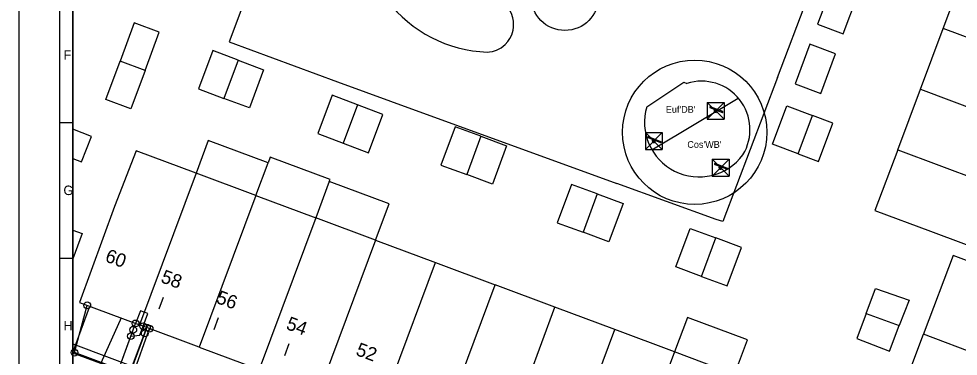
# Model space of a CAD drawing. Extents: x 192672 to 192910, y 446344 to 446512.
# Drawn here: x 192671.7 to 192741.1, y 446430.4 to 446455.3 of the extents above; entities that cross this region are included whole.
import ezdxf

# ---------------------------------------------------------------- set-up
doc = ezdxf.new("R2010")
doc.units = 0
for name, color, linetype in [('1010 viewport', 7, 'Continuous'), ('B-GV-GR-BOOM-S', 7, 'Continuous'), ('B-GV-KG-GRENS_WERKGRENS-G', 7, 'Continuous'), ('B-OI-KL-()_MANTELBUIS_WATER-G', 7, 'Continuous'), ('B-OI-KL-BUISLEIDING_OLIEGASCHEMICALIEN_GASLAGEDRUK-G', 7, 'Continuous'), ('B-OI-KL-DATA-G', 7, 'Continuous'), ('B-OI-KL-DATA_GTWP-S', 7, 'Continuous'), ('B-OI-KL-DATA_KABELBED-G', 7, 'Continuous'), ('B-OI-KL-DATA_MOF-S', 7, 'Continuous'), ('B-OI-KL-ET_LS-G', 7, 'Continuous'), ('B-OI-KL-ET_LS_DELIVERYPOINT-S', 7, 'Continuous'), ('B-OI-KL-ET_LS_MOF-S', 7, 'Continuous'), ('B-OI-KL-GAS_LD_DELIVERYPOINT-S', 7, 'Continuous'), ('B-OI-KL-GAS_LD_OVERGANGSSTUK-S', 7, 'Continuous'), ('B-OI-KL-WATER-G', 7, 'Continuous'), ('Default', 7, 'Continuous'), ('grens maaiveld', 7, 'Continuous'), ('huisnummerreeks BGT', 7, 'Continuous'), ('kant open verharding', 7, 'Continuous'), ('Luifel', 7, 'Continuous'), ('N-GV-GR-BEPLANTING-G', 7, 'Continuous'), ('pand op maaiveld vlak', 7, 'Continuous'), ('speelvoorziening', 7, 'Continuous'), ('TEKST', 7, 'Continuous'), ('V-GV-IE-MEUBILAIR_WEGMEUBILAIR_SPEELTOESTEL-G', 7, 'Continuous'), ('X-XX-AL-TEKENBLAD-S', 7, 'Continuous')]:
    doc.layers.add(name, color=color, linetype=linetype)

# ---------------------------------------------------------------- blocks, each defined once
blk = doc.blocks.new('B-OI-KL-GAS_LD_DELIVERYPOINT-S')
at = {"layer": 'Default'}
blk.add_circle((0, 0), 0.25, dxfattribs=at)
blk = doc.blocks.new('B-OI-KL-GAS_LD_OVERGANGSSTUK-S')
at = {"layer": 'Default'}
blk.add_circle((0, 0), 0.25, dxfattribs=at)
blk = doc.blocks.new('B-OI-KL-ET_LS_DELIVERYPOINT-S')
at = {"layer": 'Default'}
blk.add_circle((0, 0), 0.25, dxfattribs=at)
blk = doc.blocks.new('B-OI-KL-ET_LS_MOF-S')
at = {"layer": 'Default'}
blk.add_circle((0, 0), 0.25, dxfattribs=at)
blk = doc.blocks.new('B-OI-KL-DATA_GTWP-S')
at = {"layer": 'Default'}
blk.add_circle((0, 0), 0.25, dxfattribs=at)
blk = doc.blocks.new('B-OI-KL-DATA_MOF-S')
at = {"layer": 'Default'}
blk.add_circle((0, 0), 0.25, dxfattribs=at)

msp = doc.modelspace()

# ---------------------------------------------------------------- linework, layer by layer
at = {"layer": '1010 viewport'}
msp.add_lwpolyline([(192675.743, 446509.756), (192860.643, 446509.756), (192860.643, 446345.556), (192675.743, 446345.556)], close=True, dxfattribs=at)
at = {"layer": 'B-GV-GR-BOOM-S'}
msp.add_circle((192712.077, 446456.959), 2.5, dxfattribs=at)
at = {"layer": 'B-GV-KG-GRENS_WERKGRENS-G'}
msp.add_circle((192721.667, 446446.943), 5.327, dxfattribs=at)
at = {"layer": 'B-OI-KL-()_MANTELBUIS_WATER-G'}
msp.add_lwpolyline([(192681.085, 446432.239), (192681.19, 446432.52)], dxfattribs=at)
at = {"layer": 'B-OI-KL-BUISLEIDING_OLIEGASCHEMICALIEN_GASLAGEDRUK-G'}
for points in [[(192680.197, 446432.358), (192680.372, 446432.826)], [(192681.047, 446432.092), (192681.205, 446432.515)], [(192679.039, 446428.617), (192679.125, 446428.851), (192678.947, 446428.916), (192680.197, 446432.358)], [(192679.227, 446428.548), (192679.313, 446428.783), (192679.782, 446428.611), (192681.047, 446432.092)]]:
    msp.add_lwpolyline(points, dxfattribs=at)
at = {"layer": 'B-OI-KL-DATA-G'}
for p, q in [((192675.743, 446430.671), (192676.958, 446434.017)), ((192675.743, 446430.671), (192676.958, 446434.017)), ((192677.798, 446429.859), (192675.743, 446430.624))]:
    msp.add_line(p, q, dxfattribs=at)
for points in [[(192682.396, 446434.731), (192682.079, 446433.868)], [(192677.798, 446429.859), (192679.245, 446433.081), (192679.313, 446433.219)], [(192686.48, 446433.237), (192686.153, 446432.345)], [(192691.688, 446431.332), (192691.36, 446430.438)], [(192737.667, 446407.73), (192737.22, 446407.782), (192736.663, 446407.985), (192736.03, 446408.286), (192735.626, 446408.365), (192729.863, 446410.472), (192728.465, 446411.08), (192721.146, 446413.773), (192716.247, 446415.615), (192710.715, 446417.628), (192706.774, 446419.101), (192701.477, 446421.077), (192698.04, 446422.325), (192693.262, 446424.115), (192691.867, 446424.65), (192684.239, 446427.468), (192680.591, 446428.834), (192677.798, 446429.859), (192675.743, 446430.624)]]:
    msp.add_lwpolyline(points, dxfattribs=at)
at = {"layer": 'B-OI-KL-DATA_KABELBED-G'}
msp.add_line((192675.743, 446430.671), (192676.958, 446434.017), dxfattribs=at)
for points in [[(192682.396, 446434.731), (192682.079, 446433.868)], [(192675.857, 446430.67), (192676.798, 446434.162)], [(192686.48, 446433.237), (192686.153, 446432.345)], [(192680.18, 446429.054), (192681.402, 446432.441)], [(192691.688, 446431.332), (192691.36, 446430.438)], [(192738.388, 446407.619), (192734.688, 446408.978), (192724.883, 446412.582), (192723.845, 446412.963), (192720.372, 446414.239), (192719.183, 446414.479), (192716.646, 446415.427), (192714.21, 446416.337), (192707.529, 446418.834), (192703.97, 446420.164), (192697.852, 446422.451), (192697.2, 446422.694), (192695.696, 446423.256), (192692.683, 446424.382), (192687.423, 446426.348), (192680.18, 446429.054), (192675.857, 446430.67), (192675.743, 446430.712)]]:
    msp.add_lwpolyline(points, dxfattribs=at)
at = {"layer": 'B-OI-KL-ET_LS-G'}
for points in [[(192680.934, 446432.616), (192681.284, 446433.553), (192680.722, 446433.763), (192680.372, 446432.826)], [(192680.022, 446431.889), (192680.689, 446431.96), (192680.934, 446432.616)], [(192679.46, 446428.648), (192679.552, 446428.88), (192679.002, 446429.098), (192680.022, 446431.889)]]:
    msp.add_lwpolyline(points, dxfattribs=at)
at = {"layer": 'B-OI-KL-WATER-G'}
msp.add_lwpolyline([(192679.728, 446428.609), (192681.19, 446432.52)], dxfattribs=at)
at = {"layer": 'grens maaiveld'}
for p, q in [((192727.776, 446450.988), (192734.733, 446469.332)), ((192695.28, 446450.68), (192701.299, 446448.474))]:
    msp.add_line(p, q, dxfattribs=at)
for points in [[(192706.331, 446452.863), (192706.518, 446452.877), (192706.732, 446452.916), (192707.023, 446453.007), (192707.362, 446453.181), (192707.672, 446453.423), (192707.87, 446453.641), (192708.021, 446453.863), (192708.159, 446454.143), (192708.26, 446454.473), (192708.295, 446454.703), (192708.29, 446455.149), (192708.241, 446455.406), (192708.137, 446455.709), (192707.986, 446455.995), (192707.816, 446456.224), (192707.394, 446456.89), (192705.222, 446458.158), (192705.296, 446459.943), (192704.312, 446461.578), (192703.272, 446461.519), (192701.368, 446465.65), (192700.45, 446467.928), (192697.225, 446464.769)], [(192691.747, 446465.52), (192687.282, 446453.612), (192695.28, 446450.68)], [(192727.776, 446450.988), (192723.743, 446440.355), (192723.261, 446440.509), (192715.923, 446443.165)], [(192718.128, 446448.834), (192720.866, 446450.656), (192721.084, 446450.551)], [(192701.299, 446448.474), (192710.291, 446445.203), (192715.923, 446443.165)]]:
    msp.add_lwpolyline(points, dxfattribs=at)
for centre, radius, start, end in [((192706.69, 446462.573), 9.716, 166.93585, 267.88344), ((192722.168, 446447.137), 3.582, 328.76282, 107.61496), ((192721.99, 446447.676), 4.031, 163.30738, 323.51736)]:
    msp.add_arc(centre, radius, start, end, dxfattribs=at)
at = {"layer": 'kant open verharding'}
msp.add_lwpolyline([(192675.743, 446431.332), (192697.987, 446422.959), (192719.324, 446415.141), (192720.614, 446414.897)], dxfattribs=at)
at = {"layer": 'Luifel'}
for p, q in [((192689.258, 446442.274), (192690.161, 446444.691)), ((192694.676, 446443.3), (192693.675, 446440.623))]:
    msp.add_line(p, q, dxfattribs=at)
for points in [[(192729.308, 446445.356), (192730.801, 446444.796), (192731.861, 446447.624), (192730.368, 446448.184)], [(192690.161, 446444.691), (192685.743, 446446.341), (192684.84, 446443.924)], [(192694.676, 446443.3), (192694.73, 446443.445), (192690.312, 446445.096), (192690.161, 446444.691)], [(192698.093, 446438.972), (192699.094, 446441.649), (192694.676, 446443.3)], [(192724.599, 446429.067), (192725.554, 446431.622), (192721.136, 446433.273), (192720.181, 446430.718)]]:
    msp.add_lwpolyline(points, dxfattribs=at)
at = {"layer": 'N-GV-GR-BEPLANTING-G'}
msp.add_line((192718.512, 446445.637), (192724.889, 446449.467), dxfattribs=at)
msp.add_lwpolyline([(192718.128, 446448.834), (192720.866, 446450.656), (192721.084, 446450.551)], dxfattribs=at)
for centre, radius, start, end in [((192722.168, 446447.137), 3.582, 328.76282, 107.61496), ((192721.99, 446447.676), 4.031, 163.30738, 323.51736)]:
    msp.add_arc(centre, radius, start, end, dxfattribs=at)
at = {"layer": 'pand op maaiveld vlak'}
for p, q in [((192740.015, 446454.605), (192741.693, 446459.079)), ((192738.338, 446450.129), (192740.015, 446454.605)), ((192751.233, 446450.4), (192740.015, 446454.605)), ((192681.074, 446451.51), (192679.224, 446452.192)), ((192687.949, 446452.262), (192686.895, 446449.442)), ((192736.66, 446445.654), (192738.338, 446450.129)), ((192738.338, 446450.129), (192749.556, 446445.924)), ((192696.761, 446448.973), (192695.704, 446446.144)), ((192729.308, 446445.356), (192730.368, 446448.184)), ((192705.871, 446446.648), (192704.828, 446443.814)), ((192736.66, 446445.654), (192747.878, 446441.449)), ((192684.84, 446443.924), (192680.653, 446432.721)), ((192689.258, 446442.274), (192684.84, 446443.924)), ((192689.258, 446442.274), (192685.071, 446431.07)), ((192689.258, 446442.274), (192693.675, 446440.623)), ((192714.47, 446442.392), (192713.417, 446439.561)), ((192693.675, 446440.623), (192689.489, 446429.42)), ((192698.093, 446438.972), (192693.675, 446440.623)), ((192698.093, 446438.972), (192693.906, 446427.769)), ((192698.093, 446438.972), (192702.51, 446437.321)), ((192722.176, 446436.304), (192723.223, 446439.137)), ((192698.324, 446426.118), (192702.51, 446437.321)), ((192702.51, 446437.321), (192706.928, 446435.671)), ((192702.742, 446424.467), (192706.928, 446435.671)), ((192711.346, 446434.02), (192706.928, 446435.671)), ((192707.159, 446422.816), (192711.346, 446434.02)), ((192715.763, 446432.369), (192711.346, 446434.02)), ((192734.324, 446433.557), (192736.775, 446432.672)), ((192685.071, 446431.07), (192680.653, 446432.721)), ((192711.577, 446421.166), (192715.763, 446432.369)), ((192720.181, 446430.718), (192715.763, 446432.369)), ((192746.38, 446429.084), (192738.567, 446432.027)), ((192685.071, 446431.07), (192689.489, 446429.42)), ((192720.181, 446430.718), (192715.995, 446419.515)), ((192724.599, 446429.067), (192720.181, 446430.718))]:
    msp.add_line(p, q, dxfattribs=at)
for points in [[(192731.792, 446457.737), (192730.735, 446454.918), (192732.628, 446454.215), (192733.685, 446457.034)], [(192681.074, 446451.51), (192682.119, 446454.348), (192680.269, 446455.029), (192679.224, 446452.192)], [(192729.085, 446450.517), (192730.979, 446449.814), (192732.074, 446452.735), (192730.18, 446453.439), (192729.085, 446450.517)], [(192687.949, 446452.262), (192686.068, 446452.972), (192685.011, 446450.143), (192686.895, 446449.442)], [(192681.074, 446451.51), (192680.029, 446448.672), (192678.178, 446449.354), (192679.224, 446452.192)], [(192687.949, 446452.262), (192689.829, 446451.552), (192688.778, 446448.741), (192686.895, 446449.442)], [(192696.761, 446448.973), (192694.879, 446449.681), (192693.822, 446446.852), (192695.704, 446446.144)], [(192695.704, 446446.144), (192697.585, 446445.436), (192698.642, 446448.265), (192696.761, 446448.973)], [(192729.308, 446445.356), (192727.415, 446446.06), (192728.475, 446448.888), (192730.368, 446448.184)], [(192675.743, 446445.002), (192676.376, 446444.757), (192677.105, 446446.641), (192675.743, 446447.168)], [(192705.871, 446446.648), (192703.964, 446447.349), (192702.921, 446444.515), (192704.828, 446443.814)], [(192705.871, 446446.648), (192707.778, 446445.946), (192706.735, 446443.112), (192704.828, 446443.814)], [(192684.84, 446443.924), (192680.423, 446445.575), (192678.816, 446441.474), (192676.236, 446434.372), (192680.653, 446432.721)], [(192736.66, 446445.654), (192734.983, 446441.178), (192739.086, 446439.641), (192746.201, 446436.974), (192747.878, 446441.449)], [(192714.47, 446442.392), (192712.567, 446443.096), (192711.511, 446440.267), (192713.417, 446439.561)], [(192714.47, 446442.392), (192716.372, 446441.687), (192715.323, 446438.855), (192713.417, 446439.561)], [(192675.743, 446439.714), (192676.434, 446439.457), (192675.743, 446437.601)], [(192722.176, 446436.304), (192720.279, 446437.005), (192721.326, 446439.838), (192723.223, 446439.137)], [(192722.176, 446436.304), (192724.072, 446435.603), (192725.119, 446438.436), (192723.223, 446439.137)], [(192748.571, 446434.902), (192740.758, 446437.844), (192738.627, 446432.186), (192738.567, 446432.027)], [(192734.324, 446433.557), (192735.013, 446435.41), (192737.504, 446434.553), (192736.775, 446432.672)], [(192734.324, 446433.557), (192733.634, 446431.703), (192736.045, 446430.79), (192736.775, 446432.672)], [(192744.037, 446423.324), (192736.376, 446426.21), (192738.567, 446432.027)]]:
    msp.add_lwpolyline(points, dxfattribs=at)
at = {"layer": 'speelvoorziening'}
for p, q in [((192722.794, 446448.767), (192723.156, 446448.627)), ((192723.737, 446448.466), (192722.816, 446448.822)), ((192723.336, 446448.557), (192723.716, 446448.41)), ((192718.222, 446446.547), (192718.584, 446446.407)), ((192719.165, 446446.246), (192718.244, 446446.602)), ((192718.764, 446446.337), (192719.144, 446446.19)), ((192723.149, 446444.575), (192723.511, 446444.435)), ((192724.092, 446444.274), (192723.171, 446444.63)), ((192723.691, 446444.365), (192724.071, 446444.218))]:
    msp.add_line(p, q, dxfattribs=at)
for centre in [(192723.221, 446448.527), (192718.649, 446446.307), (192723.576, 446444.335)]:
    msp.add_circle(centre, 0.1, dxfattribs=at)
for centre, radius, start, end in [((192722.805, 446448.795), 0.0297, 68.83874, 248.83874), ((192723.221, 446448.527), 0.119, 123.04996, 14.62752), ((192723.221, 446448.527), 0.1, 0, 180), ((192723.221, 446448.527), 0.1, 180, 0), ((192723.726, 446448.438), 0.0297, 248.83874, 68.83874), ((192718.233, 446446.575), 0.0297, 68.83874, 248.83874), ((192718.649, 446446.307), 0.119, 123.04996, 14.62752), ((192718.649, 446446.307), 0.1, 0, 180), ((192718.649, 446446.307), 0.1, 180, 0), ((192719.154, 446446.218), 0.0297, 248.83874, 68.83874), ((192723.16, 446444.603), 0.0297, 68.83874, 248.83874), ((192723.576, 446444.335), 0.119, 123.04996, 14.62752), ((192723.576, 446444.335), 0.1, 0, 180), ((192723.576, 446444.335), 0.1, 180, 0), ((192724.081, 446444.246), 0.0297, 248.83874, 68.83874)]:
    msp.add_arc(centre, radius, start, end, dxfattribs=at)
at = {"layer": 'V-GV-IE-MEUBILAIR_WEGMEUBILAIR_SPEELTOESTEL-G'}
for p, q in [((192722.596, 446449.152), (192723.846, 446449.152)), ((192722.596, 446449.152), (192722.596, 446447.902)), ((192722.596, 446449.152), (192723.846, 446447.902)), ((192722.596, 446447.902), (192723.846, 446449.152)), ((192723.846, 446449.152), (192723.846, 446447.902)), ((192722.596, 446447.902), (192723.846, 446447.902)), ((192718.024, 446446.932), (192719.274, 446446.932)), ((192718.024, 446446.932), (192718.024, 446445.682)), ((192718.024, 446446.932), (192719.274, 446445.682)), ((192718.024, 446445.682), (192719.274, 446446.932)), ((192719.274, 446446.932), (192719.274, 446445.682)), ((192718.024, 446445.682), (192719.274, 446445.682)), ((192722.951, 446444.96), (192724.201, 446444.96)), ((192722.951, 446444.96), (192722.951, 446443.71)), ((192722.951, 446444.96), (192724.201, 446443.71)), ((192722.951, 446443.71), (192724.201, 446444.96)), ((192724.201, 446444.96), (192724.201, 446443.71)), ((192722.951, 446443.71), (192724.201, 446443.71))]:
    msp.add_line(p, q, dxfattribs=at)
at = {"layer": 'X-XX-AL-TEKENBLAD-S'}
for p, q in [((192671.743, 446511.756), (192671.743, 446343.556)), ((192674.743, 446510.756), (192674.743, 446344.556)), ((192674.743, 446447.656), (192675.743, 446447.656)), ((192674.743, 446437.656), (192675.743, 446437.656))]:
    msp.add_line(p, q, dxfattribs=at)
msp.add_lwpolyline([(192675.743, 446345.556), (192907.543, 446345.556), (192907.543, 446509.756), (192675.743, 446509.756)], close=True, dxfattribs=at)

# ---------------------------------------------------------------- block references
at = {"layer": 'B-OI-KL-DATA_GTWP-S'}
for p in [(192676.798, 446434.162), (192681.402, 446432.441), (192675.857, 446430.67)]:
    msp.add_blockref('B-OI-KL-DATA_GTWP-S', p, dxfattribs=at)
at = {"layer": 'B-OI-KL-DATA_MOF-S'}
msp.add_blockref('B-OI-KL-DATA_MOF-S', (192675.857, 446430.67), dxfattribs=at)
at = {"layer": 'B-OI-KL-ET_LS_DELIVERYPOINT-S'}
for p in [(192680.372, 446432.826), (192680.934, 446432.616)]:
    msp.add_blockref('B-OI-KL-ET_LS_DELIVERYPOINT-S', p, dxfattribs=at)
at = {"layer": 'B-OI-KL-ET_LS_MOF-S'}
msp.add_blockref('B-OI-KL-ET_LS_MOF-S', (192680.022, 446431.889), dxfattribs=at)
at = {"layer": 'B-OI-KL-GAS_LD_DELIVERYPOINT-S'}
for p in [(192680.372, 446432.826), (192681.205, 446432.515)]:
    msp.add_blockref('B-OI-KL-GAS_LD_DELIVERYPOINT-S', p, dxfattribs=at)
at = {"layer": 'B-OI-KL-GAS_LD_OVERGANGSSTUK-S'}
for p in [(192680.197, 446432.358), (192681.047, 446432.092)]:
    msp.add_blockref('B-OI-KL-GAS_LD_OVERGANGSSTUK-S', p, dxfattribs=at)

# ---------------------------------------------------------------- texts
at = {"layer": 'huisnummerreeks BGT'}
for s, p in [('60', (192678.052, 446437.428)), ('58', (192682.167, 446435.891)), ('56', (192686.258, 446434.362)), ('54', (192691.419, 446432.434)), ('52', (192696.568, 446430.51))]:
    msp.add_text(s, height=1, rotation=339.6, dxfattribs=at).set_placement(p)
at = {"layer": 'TEKST'}
for s, p in [("Euf'DB'", (192719.535, 446448.38)), ("Cos'WB'", (192721.123, 446445.792))]:
    msp.add_text(s, height=0.5, dxfattribs=at).set_placement(p)
at = {"layer": 'X-XX-AL-TEKENBLAD-S'}
for s, p in [('F', (192675.043, 446452.306)), ('G', (192675.043, 446442.306)), ('H', (192675.043, 446432.306))]:
    msp.add_text(s, height=0.7, dxfattribs=at).set_placement(p)

doc.saveas('drawing.dxf')
